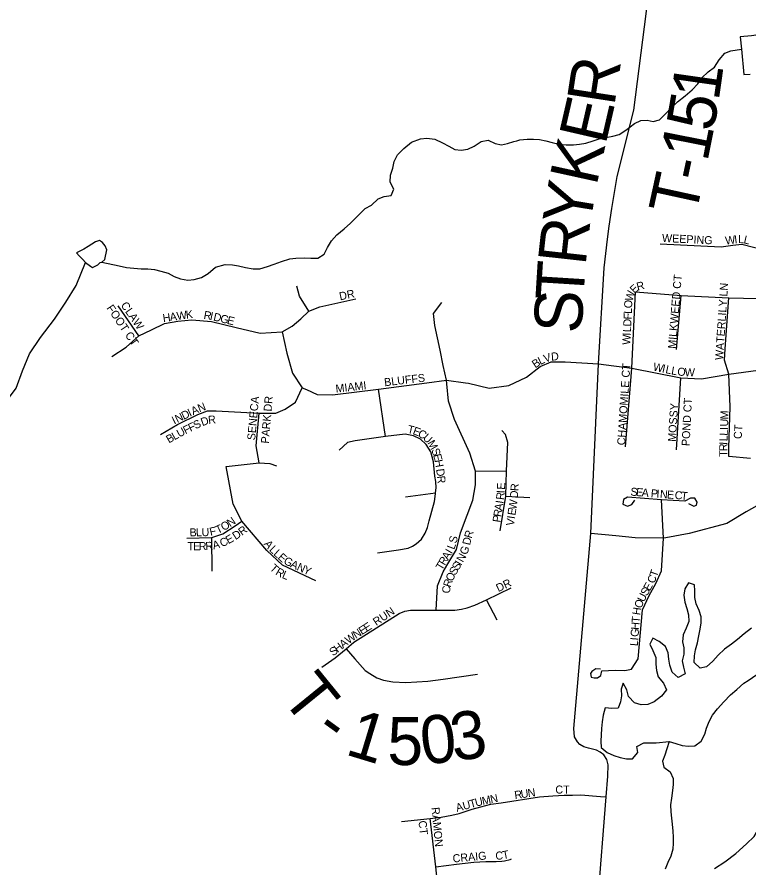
# Model space of a CAD drawing. Extents: x 0 to 1064, y 0 to 440.
# Drawn here: x 203.09 to 216.94, y 124.05 to 140.15 of the extents above; entities that cross this region are included whole.
import ezdxf

# ---------------------------------------------------------------- set-up
doc = ezdxf.new("R2010")
doc.units = 0
for name, color, linetype in [('GM_X_Minor_Lake', 7, 'Continuous'), ('GM_X_Minor_River', 7, 'Continuous'), ('GM_X_Township_Road', 7, 'Continuous'), ('GM_X_Township_Road_Text', 7, 'Continuous'), ('GM_X_Township_Subdivision', 7, 'Continuous'), ('GM_X_Township_Subdivision_Text', 7, 'Continuous'), ('GM_X_US_Route', 7, 'Continuous')]:
    doc.layers.add(name, color=color, linetype=linetype)

msp = doc.modelspace()

# ---------------------------------------------------------------- linework, layer by layer
at = {"layer": 'GM_X_Minor_Lake'}
for points in [[(218.31, 139.428), (218.183, 139.506), (218.068, 139.581), (217.954, 139.65), (217.84, 139.749), (217.714, 139.811), (217.587, 139.844), (217.465, 139.84), (217.349, 139.829), (217.234, 139.819), (217.112, 139.815), (216.99, 139.799), (216.771, 139.778)], [(216.771, 139.778), (216.795, 139.544)], [(216.795, 139.544), (216.844, 139.066), (216.96, 139.07)], [(204.75, 135.563), (204.791, 135.745), (204.756, 135.824), (204.709, 135.886), (204.649, 135.924), (204.576, 135.902), (204.434, 135.814), (204.353, 135.762), (204.218, 135.692), (204.265, 135.636), (204.336, 135.562), (204.389, 135.506)], [(204.389, 135.506), (204.479, 135.436), (204.521, 135.411), (204.619, 135.463), (204.661, 135.506), (204.696, 135.513), (204.75, 135.563)], [(216.984, 128.589), (216.849, 128.482), (216.725, 128.375), (216.608, 128.285), (216.473, 128.19), (216.356, 128.077), (216.256, 127.963), (216.133, 127.856), (216.017, 127.833), (215.903, 127.938), (215.906, 128.066), (215.926, 128.181), (215.964, 128.308), (215.991, 128.441), (216.017, 128.568), (216.032, 128.69), (216.033, 128.805), (215.999, 128.921), (215.94, 129.049), (215.918, 129.171), (215.914, 129.293), (215.91, 129.408), (215.795, 129.447), (215.726, 129.332), (215.706, 129.211), (215.728, 129.083), (215.762, 128.961)], [(215.762, 128.961), (215.797, 128.839), (215.801, 128.711), (215.75, 128.591), (215.693, 128.464), (215.679, 128.331), (215.707, 128.215), (215.706, 128.099), (215.673, 127.972), (215.701, 127.85), (215.73, 127.722), (215.601, 127.657), (215.487, 127.756), (215.441, 127.885), (215.424, 128.001), (215.408, 128.122), (215.361, 128.238), (215.241, 128.338), (215.121, 128.4), (215.064, 128.286), (215.123, 128.163), (215.176, 128.035), (215.179, 127.907), (215.19, 127.786), (215.224, 127.67), (215.319, 127.546), (215.378, 127.418), (215.285, 127.304), (215.143, 127.191), (215.027, 127.144), (214.899, 127.14), (214.772, 127.172), (214.659, 127.296), (214.63, 127.424), (214.559, 127.546), (214.521, 127.432), (214.525, 127.31), (214.511, 127.195), (214.466, 127.074), (214.345, 127.07), (214.217, 127.078), (214.178, 126.939), (214.164, 126.818), (214.15, 126.69), (214.142, 126.569), (214.134, 126.447), (214.144, 126.332), (214.258, 126.233), (214.384, 126.176), (214.505, 126.138), (214.621, 126.112), (214.736, 126.116), (214.835, 126.236), (214.819, 126.351), (214.948, 126.416), (215.063, 126.42), (215.185, 126.419), (215.429, 126.445)], [(216.925, 127.6), (217.091, 127.713)], [(215.429, 126.445), (215.556, 126.407), (215.677, 126.368), (215.798, 126.354), (215.914, 126.364), (216.037, 126.448), (216.106, 126.58), (216.138, 126.695), (216.189, 126.822), (216.252, 126.942), (216.345, 127.062), (216.462, 127.194), (216.592, 127.326), (216.71, 127.427), (216.839, 127.547), (216.925, 127.6)]]:
    msp.add_lwpolyline(points, dxfattribs=at)
at = {"layer": 'GM_X_Minor_River'}
for points in [[(212.545, 137.813), (212.604, 137.827), (212.744, 137.843), (212.86, 137.841), (212.975, 137.833), (213.096, 137.813), (213.217, 137.781), (213.351, 137.748), (213.478, 137.734), (213.618, 137.738), (213.734, 137.748), (213.855, 137.765), (213.99, 137.811), (214.106, 137.846), (214.234, 137.874), (214.362, 137.902), (214.484, 137.931), (214.607, 138.014), (214.774, 138.139), (214.896, 138.198), (215.012, 138.202), (215.127, 138.176), (215.249, 138.21), (215.36, 138.324), (215.466, 138.438), (215.589, 138.551), (215.731, 138.664), (215.866, 138.778), (215.972, 138.891), (216.047, 139.006), (216.164, 139.119), (216.287, 139.208), (216.374, 139.341), (216.48, 139.473), (216.596, 139.513), (216.795, 139.544)], [(204.696, 135.513), (205.026, 135.445), (205.165, 135.412), (205.299, 135.398), (205.438, 135.39), (205.566, 135.388), (205.693, 135.373), (205.814, 135.347), (205.948, 135.309), (206.062, 135.246), (206.183, 135.202), (206.322, 135.175), (206.444, 135.185), (206.584, 135.226), (206.707, 135.303), (206.849, 135.422), (207.026, 135.468), (207.166, 135.465), (207.281, 135.445), (207.414, 135.413), (207.56, 135.386), (207.682, 135.39), (207.828, 135.431), (207.957, 135.477), (208.097, 135.53), (208.25, 135.576), (208.366, 135.592), (208.524, 135.596), (208.651, 135.588), (208.785, 135.591), (208.902, 135.669), (208.965, 135.789), (209.04, 135.916), (209.139, 136.029), (209.281, 136.143), (209.398, 136.25), (209.528, 136.376), (209.676, 136.531), (209.799, 136.596), (209.923, 136.716), (210.039, 136.756), (210.167, 136.778), (210.217, 136.893), (210.153, 137.028), (210.155, 137.161), (210.2, 137.294), (210.226, 137.422), (210.289, 137.548), (210.407, 137.668), (210.555, 137.787), (210.726, 137.851), (210.842, 137.861), (210.993, 137.841), (211.138, 137.772), (211.259, 137.709), (211.373, 137.646), (211.494, 137.632), (211.622, 137.654), (211.739, 137.707), (211.874, 137.796), (212.008, 137.825), (212.135, 137.762), (212.256, 137.736), (212.372, 137.758), (212.488, 137.799), (212.545, 137.813)], [(200.399, 131.176), (200.662, 131.25), (200.966, 131.444), (201.27, 131.608), (201.605, 131.833), (201.909, 131.96), (202.231, 132.185), (202.54, 132.489), (202.841, 132.817), (203.076, 133.133), (203.197, 133.455), (203.329, 133.777), (203.534, 134.092), (203.799, 134.433), (204.016, 134.755), (204.209, 135.07), (204.389, 135.506)], [(215.429, 126.445), (215.384, 126.306), (215.345, 126.185), (215.301, 126.07), (215.329, 125.955), (215.449, 125.868), (215.502, 125.745), (215.506, 125.63), (215.492, 125.514), (215.471, 125.369), (215.457, 125.242), (215.461, 125.114), (215.471, 124.992), (215.487, 124.877), (215.497, 124.749), (215.508, 124.633), (215.506, 124.518), (215.498, 124.403), (215.459, 124.276), (215.402, 124.155), (215.352, 124.028)]]:
    msp.add_lwpolyline(points, dxfattribs=at)
at = {"layer": 'GM_X_Township_Road'}
for points in [[(214.077, 123.401), (214.238, 125.397), (214.27, 125.786), (214.276, 126.004), (214.247, 126.1), (214.193, 126.188), (214.121, 126.243), (214.054, 126.277), (213.902, 126.315), (213.817, 126.342), (213.741, 126.384), (213.697, 126.437), (213.641, 126.534), (213.625, 126.689), (213.946, 130.378), (214.09, 133.592), (214.2, 135.408), (214.264, 135.95), (214.292, 136.198), (214.347, 136.528), (214.448, 137.134), (214.76, 138.391), (215.102, 141.059)], [(210.44, 131.072), (211.009, 131.146)], [(209.318, 128.198), (209.481, 128.01), (209.675, 127.784), (209.763, 127.728), (209.898, 127.65), (210.023, 127.606), (210.202, 127.574), (210.45, 127.562), (210.863, 127.587), (211.152, 127.624), (211.801, 127.718)]]:
    msp.add_lwpolyline(points, dxfattribs=at)
at = {"layer": 'GM_X_Township_Subdivision'}
for points in [[(215.26, 135.862), (216.412, 135.807), (216.632, 135.835), (216.802, 135.853), (217.025, 135.796), (217.248, 135.739), (218.386, 135.69), (221.865, 135.469), (221.986, 135.414), (222.023, 135.262), (222.011, 135.062), (221.886, 133.268), (221.879, 133.212), (221.835, 133.05), (221.744, 132.88), (221.585, 132.657)], [(208.613, 134.588), (208.438, 134.868), (208.382, 135.062)], [(204.885, 133.728), (205.153, 133.909), (205.396, 134.12), (205.633, 134.233), (205.882, 134.351), (206.132, 134.395), (206.4, 134.426), (206.768, 134.389), (207.235, 134.276), (207.69, 134.17), (208.108, 134.195), (208.295, 134.301), (208.463, 134.445), (208.613, 134.588), (208.818, 134.669), (209.504, 134.819)], [(214.72, 133.507), (214.794, 134.956), (215.656, 134.886), (216.558, 134.838), (217.399, 134.823), (218.315, 134.755)], [(215.569, 133.859), (215.656, 134.886)], [(216.558, 133.395), (216.475, 133.657), (216.487, 133.875), (216.558, 134.838)], [(205.396, 134.12), (205.003, 134.688)], [(211.094, 133.849), (210.994, 134.317), (210.969, 134.541), (211.131, 134.753)], [(208.108, 134.195), (208.195, 133.79), (208.301, 133.416), (208.488, 133.135), (208.569, 133.104), (208.769, 133.011), (209.062, 133.005), (209.93, 133.108), (210.845, 133.232)], [(211.222, 133.214), (211.215, 133.283), (211.156, 133.556), (211.094, 133.849)], [(211.575, 133.231), (211.63, 133.223), (212.023, 133.129), (212.397, 133.179), (212.727, 133.341), (212.989, 133.541), (213.195, 133.628), (213.463, 133.628), (214.09, 133.592)], [(214.09, 133.592), (214.72, 133.507), (215.647, 133.324), (216.042, 133.308), (216.558, 133.395), (217.253, 133.49), (218.153, 133.498), (219.128, 133.431), (219.878, 133.342), (220.397, 133.223), (220.783, 133.079), (221.14, 132.9), (221.585, 132.657), (221.98, 132.431), (222.654, 132.215), (223, 131.994), (223.212, 131.812), (223.542, 131.433), (223.866, 130.903)], [(214.604, 132.018), (214.72, 133.507)], [(216.97, 131.798), (216.559, 131.834), (216.559, 132.003), (216.583, 132.776), (216.558, 133.395)], [(210.845, 133.232), (211.215, 133.283), (211.575, 133.231)], [(211.018, 128.929), (211.044, 129.392), (211.156, 129.654), (211.243, 129.803), (211.406, 130.078), (211.48, 130.389), (211.605, 130.726), (211.717, 131.013), (211.767, 131.3), (211.767, 131.561), (211.655, 131.898), (211.368, 132.534), (211.256, 132.883), (211.222, 133.214)], [(215.565, 131.963), (215.647, 133.324)], [(205.808, 132.256), (206.125, 132.443), (206.512, 132.63), (206.693, 132.699), (206.861, 132.699), (207.671, 132.655), (207.989, 132.655), (208.164, 132.73), (208.357, 132.867), (208.488, 133.135)], [(210.062, 132.214), (209.93, 133.108)], [(207.671, 131.72), (207.615, 132.038), (207.671, 132.655)], [(209.914, 130.016), (210.31, 130.072), (210.494, 130.101), (210.574, 130.137), (210.641, 130.181), (210.744, 130.275), (210.814, 130.385), (210.854, 130.495), (210.888, 130.622), (210.988, 130.987), (211.006, 131.128), (211.009, 131.146), (211.024, 131.245), (211.017, 131.361), (210.995, 131.464), (210.969, 131.733), (210.919, 131.926), (210.835, 132.063), (210.726, 132.163), (210.592, 132.225), (210.436, 132.259), (210.062, 132.214), (209.489, 132.136), (209.344, 132.099), (209.183, 131.954)], [(212.235, 130.427), (212.341, 131.085), (212.35, 131.568), (212.378, 132.101), (212.334, 132.25), (212.266, 132.328)], [(208.744, 129.482), (208.114, 129.782), (207.815, 130.056), (207.347, 130.611), (207.179, 130.935), (207.047, 131.645), (207.671, 131.72)], [(207.671, 131.72), (207.871, 131.702), (208.002, 131.658)], [(211.767, 131.561), (212.35, 131.568)], [(219.029, 128.631), (219.055, 128.634), (219.508, 128.711), (220.524, 128.871), (220.849, 129.014), (221.017, 129.171), (221.108, 129.354), (221.163, 129.533), (221.182, 129.759), (221.156, 130.019), (220.838, 130.447), (220.581, 130.639), (220.261, 130.911), (220.027, 131.009), (218.766, 131.104), (217.72, 131.186), (217.446, 131.103), (216.885, 130.787), (216.522, 130.566), (215.809, 130.378), (215.369, 130.298)], [(212.341, 131.085), (212.796, 131.063)], [(214.127, 127.813), (214.044, 127.821), (213.964, 127.769), (213.942, 127.728), (213.953, 127.659), (214.011, 127.645), (214.074, 127.645), (214.135, 127.695), (214.157, 127.78), (214.405, 127.791), (214.592, 127.788), (214.716, 127.81), (214.843, 128.006), (214.922, 128.934), (215.049, 129.204), (215.178, 129.434), (215.282, 129.671), (215.319, 130.289), (215.286, 131.017)], [(215.794, 130.947), (215.894, 130.895), (215.946, 130.917), (215.957, 130.973), (215.916, 131.051), (215.831, 131.051), (215.727, 130.991), (215.286, 131.017), (214.644, 131.066), (214.563, 131.021), (214.555, 130.936), (214.644, 130.899), (214.726, 130.928), (214.782, 131.01)], [(206.303, 130.29), (206.777, 130.302), (206.983, 130.371), (207.216, 130.523), (207.347, 130.611)], [(206.78, 129.669), (206.777, 130.302)], [(214.42, 130.334), (213.946, 130.378)], [(215.369, 130.298), (215.319, 130.289), (214.785, 130.3), (214.42, 130.334)], [(208.857, 127.847), (209.111, 128.029), (209.318, 128.198), (209.462, 128.321), (210.321, 128.868), (210.429, 128.91), (210.533, 128.931), (211.018, 128.929), (211.376, 128.929), (211.498, 128.949), (211.61, 128.973), (211.754, 129.025), (211.975, 129.125), (212.443, 129.353)], [(212.177, 128.738), (211.975, 129.125)], [(210.364, 124.932), (210.908, 124.986), (211.117, 125.013), (211.319, 125.051), (211.454, 125.083), (211.57, 125.118), (211.7, 125.163), (211.863, 125.208), (212.058, 125.258), (212.248, 125.285), (212.977, 125.393), (213.226, 125.416), (213.443, 125.43), (213.602, 125.43), (213.76, 125.434), (214.131, 125.403), (214.238, 125.397)], [(211.093, 123.351), (211.012, 124.068), (210.908, 124.986)], [(211.012, 124.068), (211.403, 124.12), (211.735, 124.159), (211.962, 124.175), (212.159, 124.175), (212.263, 124.177), (212.317, 124.186), (212.421, 124.213), (212.449, 124.222)]]:
    msp.add_lwpolyline(points, dxfattribs=at)
at = {"layer": 'GM_X_US_Route'}
msp.add_lwpolyline([(216.289, 124.042), (216.481, 124.164), (216.692, 124.322), (216.892, 124.505), (217.035, 124.646), (217.125, 124.796), (217.22, 125.181), (217.432, 125.586), (217.622, 125.911), (217.736, 126.065), (217.86, 126.193), (218.105, 126.396), (221.346, 128.013), (221.996, 128.334), (224.529, 129.817), (226.12, 130.822), (226.762, 131.237), (227.041, 131.416)], dxfattribs=at)

# ---------------------------------------------------------------- texts
at = {"layer": 'GM_X_Township_Road_Text'}
for s, rotation, p in [('R', 81.2617, (214.39, 138.453)), ('1', 81.9354, (216.365, 138.549)), ('5', 80.0718, (216.264, 137.965)), ('E', 77.0324, (214.224, 137.718)), ('1', 78.807, (216.151, 137.395)), ('K', 77.6506, (214.053, 136.939)), ('-', 77.9703, (216.07, 137.015)), ('T', 77.6915, (215.924, 136.346)), ('Y', 80.7066, (213.926, 136.162)), ('R', 83.6995, (213.846, 135.433)), ('T', 86.4319, (213.805, 134.766)), ('S', 86.9625, (213.772, 134.155)), ('T', 309.1411, (208.065, 127.274)), ('1', 343.0868, (209.277, 126.205)), ('5', 359.7235, (210.096, 125.999)), ('0', 6.4249, (210.772, 126.002)), ('3', 7.8442, (211.352, 126.068)), ('-', 324.0386, (208.681, 126.57))]:
    msp.add_text(s, height=0.909, rotation=rotation, dxfattribs=at).set_placement(p)
at = {"layer": 'GM_X_Township_Subdivision_Text'}
for s, height, rotation, p in [('WEEPING', 0.1515, 357.2313, (215.291, 135.898)), ('W', 0.152, 7.4358, (216.499, 135.845)), ('I', 0.152, 7.4609, (216.671, 135.867)), ('L', 0.152, 358.4969, (216.731, 135.876)), ('L', 0.152, 347.0771, (216.829, 135.874)), ('MILKWEED CT', 0.15152, 85.2856, (215.555, 133.872)), ('R', 0.152, 14.5228, (214.833, 134.974)), ('DR', 0.1515, 11.895, (209.204, 134.791)), ('W', 0.152, 72.6137, (214.732, 134.762)), ('E', 0.152, 43.5682, (214.773, 134.911)), ('WATERLILY LN', 0.15152, 86.1505, (216.448, 133.658)), ('FOOT CT', 0.1515, 304.2498, (204.778, 134.646)), ('CLAW', 0.1515, 304.8776, (205.046, 134.7)), ('L', 0.152, 87.1365, (214.722, 134.533)), ('O', 0.152, 87.1365, (214.727, 134.639)), ('H', 0.152, 8.4021, (205.859, 134.378)), ('A', 0.152, 8.4225, (205.991, 134.398)), ('W', 0.152, 8.4036, (206.123, 134.417)), ('K', 0.152, 6.6805, (206.293, 134.442)), ('R', 0.152, 350.2902, (206.614, 134.445)), ('I', 0.152, 348.6043, (206.731, 134.425)), ('D', 0.152, 346.9022, (206.796, 134.412)), ('G', 0.152, 346.4303, (206.925, 134.382)), ('E', 0.152, 346.4294, (207.055, 134.35)), ('F', 0.152, 87.1365, (214.717, 134.426)), ('D', 0.152, 87.1365, (214.71, 134.293)), ('I', 0.152, 87.1365, (214.701, 134.12)), ('L', 0.152, 87.1365, (214.705, 134.186)), ('W', 0.152, 87.1365, (214.693, 133.947)), ('B', 0.152, 33.7507, (212.896, 133.503)), ('L', 0.152, 25.2084, (212.99, 133.567)), ('V', 0.152, 18.5939, (213.083, 133.611)), ('D', 0.152, 3.0174, (213.198, 133.651)), ('CHAMOMILE CT', 0.15152, 86.2571, (214.595, 132.045)), ('W', 0.152, 347.9067, (215.115, 133.467)), ('I', 0.152, 347.9067, (215.285, 133.431)), ('L', 0.152, 347.9067, (215.35, 133.417)), ('L', 0.152, 349.9222, (215.46, 133.393)), ('O', 0.152, 353.9533, (215.577, 133.373)), ('W', 0.152, 357.9844, (215.721, 133.358)), ('BLUFFS', 0.1515, 6.7106, (210.046, 133.165)), ('MIAMI', 0.1515, 6.4797, (209.126, 133.045)), ('SENECA', 0.1515, 84.7129, (207.595, 132.139)), ('PARK DR', 0.1515, 85.1585, (207.854, 132.077)), ('POND CT', 0.1515, 87.0908, (215.815, 132.031)), ('D', 0.152, 25.8223, (206.244, 132.529)), ('I', 0.152, 25.8223, (206.364, 132.587)), ('A', 0.152, 24.1889, (206.423, 132.616)), ('N', 0.152, 21.3388, (206.543, 132.67)), ('MOSSY', 0.1515, 86.4256, (215.555, 132.112)), ('I', 0.152, 25.8223, (206.064, 132.442)), ('N', 0.152, 25.8223, (206.124, 132.471)), ('D', 0.152, 19.2643, (206.597, 132.41)), ('R', 0.152, 5.9861, (206.714, 132.452)), ('M', 0.152, 87.8688, (216.547, 132.535)), ('U', 0.152, 28.1586, (206.161, 132.193)), ('F', 0.152, 26.5406, (206.278, 132.255)), ('F', 0.152, 25.8686, (206.373, 132.302)), ('S', 0.152, 25.4774, (206.468, 132.349)), ('T', 0.152, 347.163, (210.467, 132.285)), ('E', 0.152, 339.8885, (210.567, 132.263)), ('U', 0.152, 87.8797, (216.543, 132.402)), ('CT', 0.1515, 86.8215, (216.801, 132.164)), ('B', 0.152, 29.7057, (205.965, 132.082)), ('L', 0.152, 29.1687, (206.069, 132.141)), ('C', 0.152, 329.8485, (210.66, 132.229)), ('U', 0.152, 317.7675, (210.757, 132.174)), ('L', 0.152, 87.8961, (216.532, 132.122)), ('L', 0.152, 87.8688, (216.536, 132.228)), ('I', 0.152, 87.8915, (216.54, 132.335)), ('M', 0.152, 300.086, (210.848, 132.093)), ('R', 0.152, 89.0771, (216.528, 131.936)), ('I', 0.152, 87.9452, (216.53, 132.055)), ('S', 0.152, 290.4313, (210.926, 131.961)), ('T', 0.152, 89.9453, (216.528, 131.83)), ('E', 0.152, 285.2024, (210.962, 131.865)), ('H', 0.152, 280.2384, (210.989, 131.765)), ('D', 0.152, 277.9601, (211.019, 131.596)), ('R', 0.152, 276.0103, (211.037, 131.465)), ('E', 0.152, 86.772, (212.321, 131.205)), ('R', 0.152, 86.6626, (212.577, 131.178)), ('R', 0.152, 83.2116, (212.302, 131.009)), ('I', 0.152, 86.4149, (212.317, 131.137)), ('D', 0.152, 84.6428, (212.564, 131.04)), ('S', 0.152, 355.5154, (214.692, 131.098)), ('E', 0.152, 355.5154, (214.798, 131.09)), ('A', 0.152, 355.4923, (214.904, 131.082)), ('P', 0.152, 355.4882, (215.077, 131.068)), ('I', 0.152, 355.542, (215.184, 131.06)), ('N', 0.152, 355.4923, (215.25, 131.055)), ('E', 0.152, 355.5188, (215.383, 131.044)), ('C', 0.152, 355.5326, (215.53, 131.033)), ('T', 0.152, 353.5934, (215.648, 131.023)), ('A', 0.152, 81.0694, (212.27, 130.805)), ('I', 0.152, 81.0478, (212.291, 130.937)), ('W', 0.152, 82.4106, (212.536, 130.822)), ('R', 0.152, 81.0722, (212.251, 130.686)), ('E', 0.152, 81.5049, (212.519, 130.714)), ('N', 0.152, 34.683, (207.124, 130.497)), ('P', 0.152, 81.0856, (212.235, 130.581)), ('V', 0.152, 81.4649, (212.49, 130.516)), ('I', 0.152, 81.4996, (212.51, 130.648)), ('B', 0.152, 0.85, (206.357, 130.325)), ('L', 0.152, 0.8469, (206.477, 130.327)), ('U', 0.152, 0.8604, (206.584, 130.328)), ('F', 0.152, 12.6924, (206.751, 130.335)), ('T', 0.152, 24.9699, (206.888, 130.369)), ('O', 0.152, 31.0572, (207.001, 130.423)), ('R', 0.152, 37.0919, (207.348, 130.332)), ('C', 0.152, 23.5994, (206.965, 130.119)), ('E', 0.152, 29.4317, (207.09, 130.175)), ('D', 0.152, 32.7121, (207.225, 130.253)), ('S', 0.152, 76.6273, (211.404, 130.184)), ('D', 0.152, 76.9022, (211.661, 130.149)), ('R', 0.152, 72.8937, (211.691, 130.276)), ('T', 0.152, 0, (206.316, 130.064)), ('E', 0.152, 0.0206, (206.423, 130.064)), ('R', 0.152, 0.5284, (206.531, 130.064)), ('R', 0.152, 3.295, (206.659, 130.066)), ('A', 0.152, 14.1899, (206.81, 130.078)), ('A', 0.152, 309.008, (207.753, 130.179)), ('L', 0.152, 316.3959, (207.852, 130.06)), ('L', 0.152, 69.5597, (211.361, 130.065)), ('G', 0.152, 70.952, (211.604, 129.965)), ('L', 0.152, 317.8843, (207.932, 129.983)), ('E', 0.152, 318.0789, (208.012, 129.911)), ('A', 0.152, 59.4336, (211.247, 129.866)), ('I', 0.152, 59.4823, (211.315, 129.981)), ('N', 0.152, 61.0432, (211.528, 129.822)), ('T', 0.152, 316.5649, (207.862, 129.707)), ('G', 0.152, 330.726, (208.121, 129.819)), ('A', 0.152, 335.7083, (208.25, 129.747)), ('N', 0.152, 335.6646, (208.371, 129.692)), ('T', 0.152, 59.4486, (211.132, 129.671)), ('R', 0.152, 59.478, (211.186, 129.763)), ('S', 0.152, 59.3665, (211.438, 129.669)), ('I', 0.152, 60.2007, (211.494, 129.762)), ('R', 0.152, 329.8966, (207.969, 129.611)), ('L', 0.152, 337.1415, (208.092, 129.542)), ('Y', 0.152, 335.6447, (208.493, 129.638)), ('S', 0.152, 59.0316, (211.383, 129.576)), ('T', 0.152, 70.8255, (215.196, 129.544)), ('R', 0.152, 70.9736, (211.29, 129.35)), ('O', 0.152, 64.8035, (211.328, 129.459)), ('DR', 0.1515, 25.1968, (212.197, 129.269)), ('C', 0.152, 65.5648, (215.141, 129.42)), ('C', 0.152, 84.9419, (211.282, 129.24)), ('S', 0.152, 60.8074, (215.01, 129.187)), ('E', 0.152, 60.55, (215.062, 129.28)), ('U', 0.152, 63.1221, (214.951, 129.069)), ('O', 0.152, 66.3393, (214.898, 128.949)), ('RUN', 0.1515, 33.6859, (209.887, 128.627)), ('H', 0.152, 81.0694, (214.88, 128.827)), ('E', 0.152, 32.757, (209.705, 128.512)), ('H', 0.152, 85.4705, (214.859, 128.551)), ('T', 0.152, 85.4941, (214.869, 128.684)), ('W', 0.152, 35.9989, (209.364, 128.282)), ('N', 0.152, 32.8836, (209.503, 128.382)), ('E', 0.152, 32.7352, (209.615, 128.455)), ('G', 0.152, 85.4881, (214.848, 128.418)), ('A', 0.152, 38.0897, (209.261, 128.2)), ('I', 0.152, 85.4505, (214.843, 128.352)), ('S', 0.152, 38.105, (209.072, 128.052)), ('H', 0.152, 38.1137, (209.156, 128.118)), ('L', 0.152, 85.4882, (214.835, 128.245)), ('R', 0.152, 8.2366, (212.512, 125.352)), ('U', 0.152, 8.2424, (212.631, 125.369)), ('N', 0.152, 8.2259, (212.763, 125.388)), ('CT', 0.1515, 0, (213.276, 125.458)), ('U', 0.152, 15.2229, (211.544, 125.146)), ('T', 0.152, 15.2317, (211.673, 125.181)), ('U', 0.152, 13.8825, (211.775, 125.209)), ('M', 0.152, 11.8136, (211.903, 125.24)), ('N', 0.152, 11.7086, (212.059, 125.273)), ('RAMON', 0.1515, 275.4937, (210.931, 125.193)), ('A', 0.152, 15.213, (211.415, 125.111)), ('CT', 0.1515, 276.3362, (210.686, 124.938)), ('CRAIG', 0.1515, 5.3117, (211.34, 124.152)), ('C', 0.152, 2.8673, (212.145, 124.205)), ('T', 0.152, 11.1665, (212.289, 124.214))]:
    msp.add_text(s, height=height, rotation=rotation, dxfattribs=at).set_placement(p)

doc.saveas('drawing.dxf')
